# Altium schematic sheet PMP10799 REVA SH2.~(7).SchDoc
size 431 x 279 mm; Date: Not shown in title block; ApprovedBy: Not shown in title block; CheckedBy: Not shown in title block; Author: Not shown in title block; CompanyName: Not shown in title block; Engineer: Not shown in title block; Organization: Not shown in title block; Address1: Not shown in title block; Address2: Not shown in title block; Address3: Not shown in title block; Address4: Not shown in title block; DocumentNumber: 2; Revision: Use project parameter SCH_Rev; SheetNumber: 2; SheetTotal: 2; PageSetup: Record=PageOptions¦CenterHorizontal=True¦CenterVertical=True¦PrintScale=1.00¦XCorrection=1.00¦YCorrection=1.00¦PrintKind=0¦BorderSize=5000000¦LeftOffset=0¦BottomOffset=0¦Orientation=2¦PaperLength=1000¦PaperWidth=1000¦Scale=100¦PaperSource=15¦PrintQuality=600¦MediaType=1¦DitherType=10¦PaperKind=Letter¦PrintScaleMode=1
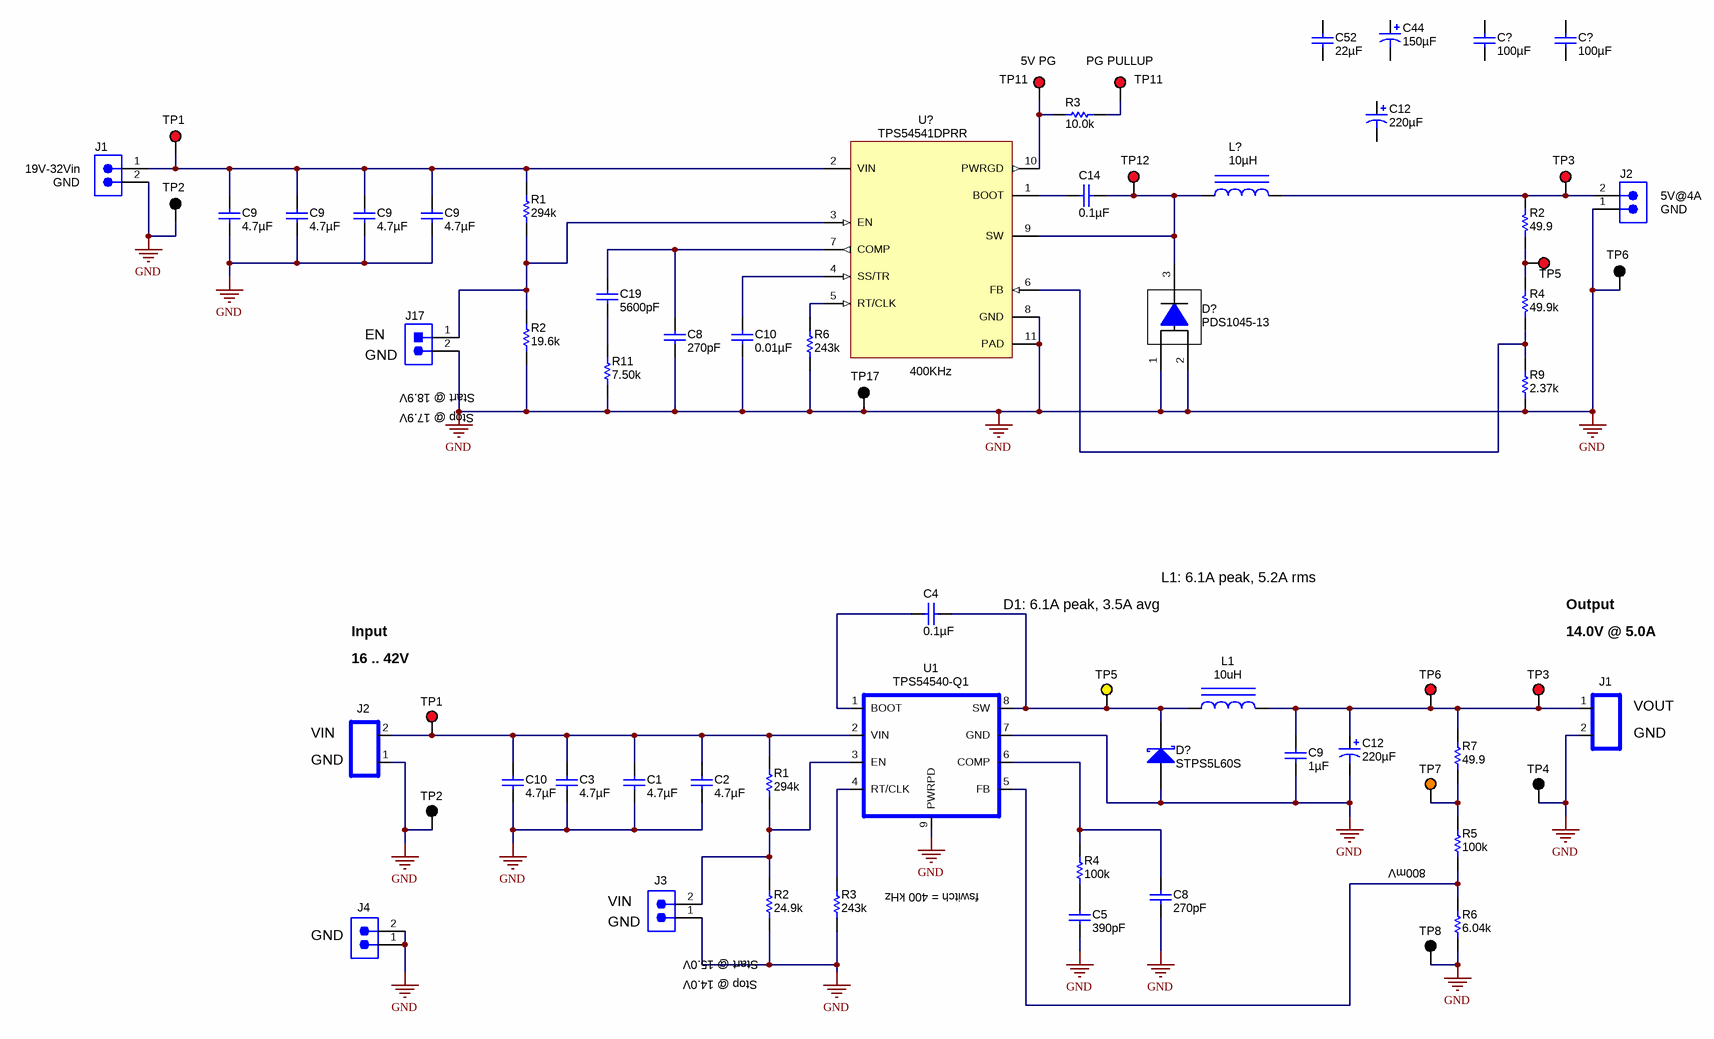
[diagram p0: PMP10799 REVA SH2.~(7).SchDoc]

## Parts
(Parts that share a designator on the sheet are numbered #1, #2 ... from top to bottom, then left to right.)
C1  ValueDisplayed: 4.7µF  [1210]  (hidden comment: GRM32ER71H475KA88L)
C2  ValueDisplayed: 4.7µF  [1210]  (hidden comment: GRM32ER71H475KA88L)
C3  ValueDisplayed: 4.7µF  [1210]  (hidden comment: GRM32ER71H475KA88L)
C4  ValueDisplayed: 0.1µF  [0603]  (hidden comment: C0603C104K8RACTU)
C5  ValueDisplayed: 390pF  [0603]  (hidden comment: GRM188R71H391KA01D)
C8#1  ValueDisplayed: 270pF  [0603]  (hidden comment: GRM188R71H271KA01D)
C8#2  ValueDisplayed: 270pF  [0603]  (hidden comment: GRM188R71H271KA01D)
C9#1  ValueDisplayed: 4.7µF  [1210]  (hidden comment: C3225X7R1H475M250AB)
C9#2  ValueDisplayed: 4.7µF  [1210]  (hidden comment: C3225X7R1H475M250AB)
C9#3  ValueDisplayed: 4.7µF  [1210]  (hidden comment: C3225X7R1H475M250AB)
C9#4  ValueDisplayed: 4.7µF  [1210]  (hidden comment: C3225X7R1H475M250AB)
C9#5  ValueDisplayed: 1µF  [1206]  (hidden comment: GRM31MR71H105KA88L)
C10#1  ValueDisplayed: 0.01µF  [0603]  (hidden comment: C1608X7R1H103K)
C10#2  ValueDisplayed: 4.7µF  [1210]  (hidden comment: GRM32ER71H475KA88L)
C12#1  ValueDisplayed: 220µF  [SM_RADIAL_F]  (hidden comment: EEE-FK1E221P)
C12#2  ValueDisplayed: 220µF  [SM_RADIAL_F]  (hidden comment: EEE-FK1E221P)
C14  ValueDisplayed: 0.1µF  [0603]  (hidden comment: C1608X7R1H104K)
C19  ValueDisplayed: 5600pF  [0603]  (hidden comment: C1608C0G1E562J)
C44  ValueDisplayed: 150µF  [TPB_D4]  (hidden comment: 10TPB150ML)
C52  ValueDisplayed: 22µF  [1210]  (hidden comment: C3225X7R1A226M230AC)
C?#1  ValueDisplayed: 100µF  [1206]  (hidden comment: GRM31CR60J107ME39L)
C?#2  ValueDisplayed: 100µF  [1210]  (hidden comment: C3225X5R0J107M)
D?#1  PDS1045-13  [PowerDI5]
D?#2  STPS5L60S  [SMC]
J1#1  ED555/2DS  [TERM_BLK_ED555-2DS]  (value not drawn)
J1#2  TBLK_15A_2X5.1MM  [TB_2X5.1MM]  (value not drawn)
J2#1  ED555/2DS  [TERM_BLK_ED555-2DS]  (value not drawn)
J2#2  TBLK_15A_2X5.1MM  [TB_2X5.1MM]  (value not drawn)
J3  TSW-102-07-G-S  [TSW-102-07-G-S]  (value not drawn)
J4  TSW-102-07-G-S  [TSW-102-07-G-S]  (value not drawn)
J17  PEC02SAAN  [CONN_PEC02SAAN]  (value not drawn)
L1  10uH  [SRP1250]
L?  ValueDisplayed: 10µH  [XAL8080_656]  (hidden comment: XAL8080-103ME)
R1#1  value 294k  [0603]  (hidden comment: CRCW0603294KFKEA)
R1#2  value 294k  [0603]  (hidden comment: CRCW0603294KFKEA)
R2#1  value 49.9  [0603L]  (hidden comment: CRCW060349R9FKEA)
R2#2  ValueDisplayed: 19.6k  [0603]  (hidden comment: CRCW060319K6FKEA)
R2#3  value 24.9k  [0603]  (hidden comment: CRCW060324K9FKEA)
R3#1  ValueDisplayed: 10.0k  [0603]  (hidden comment: CRCW060310K0FKEA)
R3#2  value 243k  [0603]  (hidden comment: CRCW0603243KFKEA)
R4#1  value 49.9k  [0603L]  (hidden comment: CRCW060349K9FKEA)
R4#2  value 100k  [0603]  (hidden comment: CRCW0603100KFKEA)
R5  value 100k  [0603]  (hidden comment: CRCW0603100KFKEA)
R6#1  ValueDisplayed: 243k  [0603]  (hidden comment: CRCW0603243KFKEA)
R6#2  value 6.04k  [0603]  (hidden comment: CRCW06036K04FKEA)
R7  value 49.9  [0603]  (hidden comment: CRCW060349R9FKEA)
R9  ValueDisplayed: 2.37k  [0603L]  (hidden comment: CRCW06032K37FKEA)
R11  ValueDisplayed: 7.50k  [0603]  (hidden comment: CRCW06037K50FKEA)
TP1#1  5000  [Keystone5000]  (value not drawn)
TP1#2  5010  [Keystone5010]  (value not drawn)
TP2#1  5001  [Keystone5001]  (value not drawn)
TP2#2  5011  [Keystone5011]  (value not drawn)
TP3#1  5000  [Keystone5000]  (value not drawn)
TP3#2  5010  [Keystone5010]  (value not drawn)
TP4  5011  [Keystone5011]  (value not drawn)
TP5#1  5000  [Keystone5000]  (value not drawn)
TP5#2  5014  [Keystone5014]  (value not drawn)
TP6#1  5001  [Keystone5001]  (value not drawn)
TP6#2  5010  [Keystone5010]  (value not drawn)
TP7  5013  [Keystone5013]  (value not drawn)
TP8  5011  [Keystone5011]  (value not drawn)
TP11#1  5000  [Keystone5000]  (value not drawn)
TP11#2  5000  [Keystone5000]  (value not drawn)
TP12  5000  [Keystone5000]  (value not drawn)
TP17  5001  [Keystone5001]  (value not drawn)
U1  TPS54540-Q1  [DDA-8]
U?  TPS54541DPRR  [DPR0010A]

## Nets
GND: C1.2 C2.2 C3.2 C5.2 C8#1.2 C8#2.2 C9#1.1 C9#2.1 C9#3.1 C9#4.1 C9#5.2 C10#1.2 C10#2.2 C12#2.2(-) D?#1.1(A) D?#1.2(A) D?#2.2(A) J1#1.2 J1#2.2 J2#1.1 J2#2.1 J3.1 J4.1 J4.2 J17.2 R2#2.1 R2#3.1 R3#2.1 R6#1.1 R6#2.1 R9.1 R11.1 TP2#1.1 TP2#2.1 TP4.1 TP6#1.1 TP8.1 TP17.1 U1.7(GND) U1.9(PWRPD) U?.8(GND) U?.11(PAD)
NetC1_1: C1.1 C2.1 C3.1 C10#2.1 J2#2.2 R1#2.2 TP1#2.1 U1.2(VIN)
NetC4_1: C4.1 D?#2.1(K) L1.1 TP5#2.1 U1.8(SW)
NetC4_2: C4.2 U1.1(BOOT)
NetC5_1: C5.1 R4#2.1
NetC8#1_1: C8#1.1 C19.1 U?.7(COMP)
NetC8#2_1: C8#2.1 R4#2.2 U1.6(COMP)
NetC9#1_2: C9#1.2 C9#2.2 C9#3.2 C9#4.2 J1#1.1 R1#1.2 TP1#1.1 U?.2(VIN)
NetC9#5_1: C9#5.1 C12#2.1(+) J1#2.1 L1.2 R7.2 TP3#2.1 TP6#2.1
NetC10#1_1: C10#1.1 U?.4(SS/TR)
NetC14_1: C14.1 U?.1(BOOT)
NetC14_2: C14.2 D?#1.3(K) L?.1 TP12.1 U?.9(SW)
NetC19_2: C19.2 R11.2
NetJ2#1_2: J2#1.2 L?.2 R2#1.2 TP3#1.1
NetJ3_2: J3.2 R1#2.1 R2#3.2 U1.3(EN)
NetJ17_1: J17.1 R1#1.1 R2#2.2 U?.3(EN)
NetR2#1_1: R2#1.1 R4#1.2 TP5#1.1
NetR3#1_1: R3#1.1 TP11#2.1
NetR3#1_2: R3#1.2 TP11#1.1 U?.10(PWRGD)
NetR3#2_2: R3#2.2 U1.4(RT/CLK)
NetR4#1_1: R4#1.1 R9.2 U?.6(FB)
NetR5_1: R5.1 R6#2.2 U1.5(FB)
NetR5_2: R5.2 R7.1 TP7.1
NetR6#1_2: R6#1.2 U?.5(RT/CLK)

Not connected (* = marked no-connect by the designer): C12#1 1(+) 2(-); C44 1(+) 2(-); C52 1 2; C?#1 1 2; C?#2 1 2

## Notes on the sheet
- (near TP11#1) 5V PG
- (near TP11#2) PG PULLUP
- (near J1#1) 19V-32Vin
- (near J1#1) GND
- (near J2#1) 5V@4A
- (near J2#1) GND
- (near J17) EN
- (near J17) GND
- (near J17) Start @ 18.9V
- (near U?) 400KHz
- Stop @ 17.9V
- L1: 6.1A peak, 5.2A rms
- Input
- 16 .. 42V
- D1: 6.1A peak, 3.5A avg
- Output
- 14.0V @ 5.0A
- (near J1#2) VOUT
- (near J2#2) VIN
- (near J2#2) GND
- (near J1#2) GND
- 800mV
- (near J4) GND
- (near J3) VIN
- (near J3) GND
- (near R3#2) fswitch = 400 kHz
- (near J3) Start @ 15.0V
- Stop @ 14.0V

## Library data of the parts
C1-C3 C10#2 = GRM32ER71H475KA88L: CAP, CERM, 4.7uF, 50V, +/-10%, X7R, 1210; Manufacturer: MuRata; Polarized: N; CompType: Capacitor; U/M: EA; Cap_F: 0.0000047; Tolerance_%: 10; ESR_Ohm: 0.002; Value1: 0.002 ohm; VDC_V: 50; TaMin_C: -55; TaMax_C: 125
C4 = C0603C104K8RACTU: CAP, CERM, 0.1uF, 10V, +/-10%, X7R, 0603; Manufacturer: Kemet; Polarized: N; CompType: Capacitor; U/M: EA; Cap_F: 0.0000001; Tolerance_%: 10; TaMin_C: -55; TaMax_C: 125
C5 = GRM188R71H391KA01D: CAP, CERM, 390pF, 50V, +/-10%, X7R, 0603; Manufacturer: MuRata; Polarized: N; CompType: Capacitor; U/M: EA; Cap_F: 0.00000000039; Tolerance_%: 10; Value1: Unknown; VDC_V: 50; TaMin_C: -55; TaMax_C: 125
C8#1 C8#2 = GRM188R71H271KA01D: CAP, CERM, 270pF, 50V, +/-10%, X7R, 0603; Manufacturer: MuRata; Polarized: N; CompType: Capacitor; U/M: EA; Cap_F: 0.00000000027; Tolerance_%: 10; Value1: Unknown; VDC_V: 50; TaMin_C: -55; TaMax_C: 125
C9#1-C9#4 = C3225X7R1E106M: CAP, CERM, 4.7uF, 50V, +/-20%, X7R, 1210; Manufacturer: TDK; Polarized: N; CompType: Capacitor; U/M: EA; Cap_F: 0.00001; Tolerance_%: 20; ESR_Ohm: 0.0027; Value1: 0.0027 ohm; VDC_V: 50; IRMS_A: 3; TaMin_C: -55; TaMax_C: 125
C9#5 = GRM31MR71H105KA88L: CAP, CERM, 1uF, 50V, +/-10%, X7R, 1206; Manufacturer: MuRata; Polarized: N; CompType: Capacitor; U/M: EA; Cap_F: 0.000001; Tolerance_%: 10; Value1: Unknown; VDC_V: 50; TaMin_C: -55; TaMax_C: 125
C10#1 = C1608X7R1H103K: CAP, CERM, 0.01 µF, 50 V, +/- 10%, X7R, 0603; Manufacturer: TDK; Polarized: N; CompType: Capacitor; Value: 0.01uF; U/M: EA; Cap_F: 0.00000001; Tolerance_%: 10; ESR_ohm: 0.0539; Value1: 0.0539 ohm; VDC_V: 50; Value2: 50V; TaMin_C: -55; TaMax_C: 125
C12#1 C12#2 = EEE-FK1E221P: CAP, AL, 220uF, 25V, +/-20%, 0.16 ohm, SMD; Manufacturer: Panasonic; Polarized: Y; CompType: Capacitor; U/M: EA; Cap_F: 0.00022; Tolerance_%: 20; VDC_V: 25; ESR_Ohm: 0.16; IRMS_A: 0.6; TaMin_C: -55; TaMax_C: 105; Cap_Case: F
C14 = C1608X7R1H104K: CAP, CERM, 0.1uF, 50V, +/-10%, X7R, 0603; Manufacturer: TDK; Polarized: N; CompType: Capacitor; U/M: EA; Cap_F: 0.0000001; Tolerance_%: 10; ESR_Ohm: 0.017; Value1: 0.017 ohm; VDC_V: 50; TaMin_C: -55; TaMax_C: 125
C19 = C1608C0G1E562J: CAP, CERM, 5600 pF, 25 V, +/- 5%, C0G/NP0, 0603; Manufacturer: TDK; Polarized: N; CompType: Capacitor; Value: 5600pF; U/M: EA; Cap_F: 0.0000000056; Tolerance_%: 5; Value1: Unknown; VDC_V: 25; Value2: 25V; TaMin_C: -55; TaMax_C: 125
C44 = 10TPB220M: CAP, 150uF, 10V, +/-20%, 0.04 ohm, SMD; Manufacturer: Panasonic; Polarized: Y; CompType: Capacitor; U/M: EA; Cap_F: 0.00022; Tolerance_%: 20; VDC_V: 10; ESR_Ohm: 0.04; IRMS_A: 3; TaMin_C: -55; TaMax_C: 105; Cap_Case: D
C52 = C3225X7R1C226M: CAP, CERM, 22 µF, 16 V, +/- 20%, X7R, 1210; Manufacturer: TDK; Polarized: N; CompType: Capacitor; Value: 22uF; U/M: EA; Cap_F: 0.000022; Tolerance_%: 20; ESR_ohm: 0.002; Value1: 0.002 ohm; VDC_V: 16; Value2: 16V; IRMS_A: 8.11; TaMin_C: -55; TaMax_C: 125
C?#1 = GRM31CR60J107ME39L: CAP, CERM, 100 µF, 6.3 V, +/- 20%, X5R, 1206; Manufacturer: MuRata; Polarized: N; CompType: Capacitor; Value: 100uF; U/M: EA; Cap_F: 0.0001; Tolerance_%: 20; ESR_ohm: 0.003; Value1: 0.003 ohm; VDC_V: 6.3; Value2: 6.3V; TaMin_C: -55; TaMax_C: 85
C?#2 = C3225X5R0J107M: CAP, CERM, 100 µF, 6.3 V, +/- 20%, X5R, 1210; Manufacturer: TDK; Polarized: N; CompType: Capacitor; Value: 100uF; U/M: EA; Cap_F: 0.0001; Tolerance_%: 20; ESR_ohm: 0.002; Value1: 0.002 ohm; VDC_V: 6.3; Value2: 6.3V; IRMS_A: 3.5; TaMin_C: -55; TaMax_C: 85
D?#1 = PDS1045-13: Diode, Schottky, 45 V, 10 A, PowerDI5; Manufacturer: Diodes Inc.; SymbolCreator: a0412235; U/M: EA; Vf_V: 0.51; Value: 45V; Value1: 10A; Value2: 0.51V; Io_A: 10; Vr_V: 45; TJmax_C: 150; RJC_CperW: 85
D?#2 = STPS5L60S: Diode, Schottky, 60 V, 5 A, SMC; Manufacturer: ST Microelectronics; U/M: EA; Vf_V: 0.53; Value: 60V; Value1: 5A; Value2: 0.53V; Io_A: 5; Vr_V: 60; TJmax_C: 150
J1#1 J2#1 = ED555/2DS: Terminal Block, 6A, 3.5mm Pitch, 2-Pos, TH; Manufacturer: On-Shore Technology, Inc.; SymbolCreator: a0412235; CompType: Connector; U/M: EA
J1#2 J2#2 = TBLK_15A_2X5.1MM: Terminal Block, 2-pin, 15-A, 5.1mm; Manufacturer: OST; PartNumber: ED120/2DS; Alternate Manufacturer: Any; Alternate PartNumber: Equivalent; area: 141600; Value: ED120/2DS
J3 J4 = TSW-102-07-G-S: Header, TH, 100mil, 2x1, Gold plated, 230 mil above insulator; Manufacturer: Samtec, Inc.; U/M: EA
J17 = PEC02SAAN: Header, 100mil, 2x1, Tin, TH; Manufacturer: Sullins Connector Solutions; SymbolCreator: a0412235; U/M: EA
L1 = SRP1250-100M: Inductor, Powdered Iron, 10uH, 10A, 17mOhm; PartNumber: SRP1270-100M; Manufacturer: Bourns; Ind_H: 10.0E-6; ValueDisplayed: 10µH; Imax_A: 16; Irms: 10A @ 40C rise; Isat: 16A @ 20% inductance drop; DCR_ohm: 0.017; Value1: 0.017 ohm; U/M: EA
L? = XAL8080-472ME: Inductor, Shielded, Composite, 10 µH, 8.7 A, 0.021 ohm, SMD; Manufacturer: Coilcraft; Value: 10uH; Ind_H: 10E-6; Imax_A: 8.7; Irms: 6.6A @ 20C rise; Isat: 10.9A @ 20% inductance drop; DCR_ohm: 21; Value2: 8.7A
R1#1 R1#2 = CRCW0603294KFKEA: RES, 294k ohm, 1%, 0.1W, 0603; Manufacturer: Vishay-Dale; CompType: Resistor; Res_ohm: 294000; Tolerance_%: 1; Power_W: 0.1; VDC_V: 75; TempCo: 100 ppm/C; EIA_Code: E96; U/M: EA
R2#1 = CRCW060349R9FKEA: RES, 49.9 ohm, 1%, 0.1W, 0603; Manufacturer: Vishay-Dale; CompType: Resistor; Value_Code: 49R9; Tolerance_%: 1; Power_W: 0.1; VDC_V: 75; TempCo: 100 ppm/C; EIA_Code: E96; U/M: EA
R2#2 = CRCW060319K6FKEA: RES, 19.6 k, 1%, 0.1 W, 0603; Manufacturer: Vishay-Dale; CompType: Resistor; Value: 19.6k; Res_ohm: 19600; Value_Code: 19k6; Tolerance_%: 1; Power_W: 0.1; Value2: 0.1W; VDC_V: 75; TempCo: 100 ppm/C; EIA_Code: E96; U/M: EA
R2#3 = CRCW060324K9FKEA: RES, 24.9k ohm, 1%, 0.1W, 0603; Manufacturer: Vishay-Dale; CompType: Resistor; Res_ohm: 24900; Value_Code: 24k9; Tolerance_%: 1; Power_W: 0.1; VDC_V: 75; TempCo: 100 ppm/C; EIA_Code: E96; U/M: EA
R3#1 = CRCW060310K0FKEA: RES, 10.0 k, 1%, 0.1 W, 0603; Manufacturer: Vishay-Dale; CompType: Resistor; Value: 10.0k; Res_ohm: 10000; Value_Code: 10k0; Tolerance_%: 1; Power_W: 0.1; Value2: 0.1W; VDC_V: 75; TempCo: 100 ppm/C; EIA_Code: E96; U/M: EA
R3#2 = CRCW0603243KFKEA: RES, 243k ohm, 1%, 0.1W, 0603; Manufacturer: Vishay-Dale; Alternate Manufacturer: Any; Alternate PartNumber: Equivalent; CompType: Resistor; Res_ohm: 243000; Tolerance_%: 1; Power_W: 0.1; VDC_V: 75; TempCo: 100 ppm/C; EIA_Code: E96; U/M: EA
R4#1 = CRCW060349K9FKEA: RES, 49.9k ohm, 1%, 0.1W, 0603; Manufacturer: Vishay-Dale; CompType: Resistor; Res_ohm: 49900; Value_Code: 49k9; Tolerance_%: 1; Power_W: 0.1; VDC_V: 75; TempCo: 100 ppm/C; EIA_Code: E96; U/M: EA
R4#2 R5 = CRCW0603100KFKEA: RES, 100k ohm, 1%, 0.1W, 0603; Manufacturer: Vishay-Dale; CompType: Resistor; Res_ohm: 100000; Tolerance_%: 1; Power_W: 0.1; VDC_V: 75; TempCo: 100 ppm/C; EIA_Code: E96; U/M: EA
R6#1 = CRCW0603243KFKEA: RES, 243 k, 1%, 0.1 W, 0603; Manufacturer: Vishay-Dale; CompType: Resistor; Value: 243k; Res_ohm: 243000; Tolerance_%: 1; Power_W: 0.1; Value2: 0.1W; VDC_V: 75; TempCo: 100 ppm/C; EIA_Code: E96; U/M: EA
R6#2 = CRCW06036K04FKEA: RES, 6.04k ohm, 1%, 0.1W, 0603; Manufacturer: Vishay-Dale; CompType: Resistor; Res_ohm: 6040; Value_Code: 6k04; Tolerance_%: 1; Power_W: 0.1; VDC_V: 75; TempCo: 100 ppm/C; EIA_Code: E96; U/M: EA
R7 = CRCW060349R9FKEA: RES, 49.9 ohm, 1%, 0.1W, 0603; Manufacturer: Vishay-Dale; Alternate Manufacturer: Any; Alternate PartNumber: Equivalent; CompType: Resistor; Value_Code: 49R9; Tolerance_%: 1; Power_W: 0.1; VDC_V: 75; TempCo: 100 ppm/C; EIA_Code: E96; U/M: EA
R9 = CRCW06032K37FKEA: RES, 2.37 k, 1%, 0.1 W, 0603; Manufacturer: Vishay-Dale; CompType: Resistor; Value: 2.37k; Res_ohm: 2370; Value_Code: 2k37; Tolerance_%: 1; Power_W: 0.1; Value2: 0.1W; VDC_V: 75; TempCo: 100 ppm/C; EIA_Code: E96; U/M: EA
R11 = CRCW06037K50FKEA: RES, 7.50 k, 1%, 0.1 W, 0603; Manufacturer: Vishay-Dale; CompType: Resistor; Value: 7.50k; Res_ohm: 7500; Value_Code: 7k50; Tolerance_%: 1; Power_W: 0.1; Value2: 0.1W; VDC_V: 75; TempCo: 100 ppm/C; EIA_Code: E96; U/M: EA
TP1#1 TP3#1 TP5#1 TP11#1 TP11#2 TP12 = 5000: Test Point, TH, Miniature, Red; Manufacturer: Keystone; CompType: Test Point Loop; U/M: EA
TP1#2 TP3#2 TP6#2 = 5010: Test Point, TH, Multipurpose, Red; Manufacturer: Keystone; CompType: Test Point Loop; U/M: EA
TP2#1 TP6#1 TP17 = 5001: Test Point, TH, Miniature, Black; Manufacturer: Keystone; CompType: Test Point Loop; U/M: EA
TP2#2 TP4 TP8 = 5011: Test Point, TH, Multipurpose, Black; Manufacturer: Keystone; CompType: Test Point Loop; U/M: EA
TP5#2 = 5014: Test Point, TH Multipurpose, Yellow; Manufacturer: Keystone; CompType: Test Point Loop; U/M: EA
TP7 = 5013: Test Point, TH, Multipurpose, Orange; Manufacturer: Keystone; CompType: Test Point Loop; U/M: EA
U1 = TPS54360DDA: IC, 42V, 5A, Low Iq, Current Mode, Non-Synchronous Monolithic Buck; Manufacturer: TI; PartNumber: TPS54540DDA; Alternate Manufacturer: None; Alternate PartNumber: Equivalent; Area: 48.94 mm; Value: TPS54540DDA
U? = TPS54361DPRQ1: 4.5-V to 42-V Input, 5-A, Step Down DC-DC Converter with Soft-Start and Eco-mode, DPR0010A; Alternate Manufacturer: None; Manufacturer: Texas Instruments; SymbolCreator: a0411947; CompType: IC; U/M: EA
